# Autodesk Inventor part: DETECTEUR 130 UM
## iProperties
Author: jost
Created: 2001-03
Part Number: DETECTEUR 130 UM
Material: Par défaut
Document SubType Name: Modélisation
Designer: jost
Control State: 0
Master: False
Checked Out: False
PropertySet Name: Design Tracking Control
Shininess: 21.0
Length Units: 11269
Angle Units: 11283
Time Units: 11279
Mass Units: 11290
Length Display Precision: 3
Angle Display Precision: 2
Compacted: False
PropertySet Name: _Private Model Information
Density: 0.0
Volumn: 0.0
Area: 0.0
PropertySet Name: Model Information
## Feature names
1. AngleRévolution1 [Revolution]
